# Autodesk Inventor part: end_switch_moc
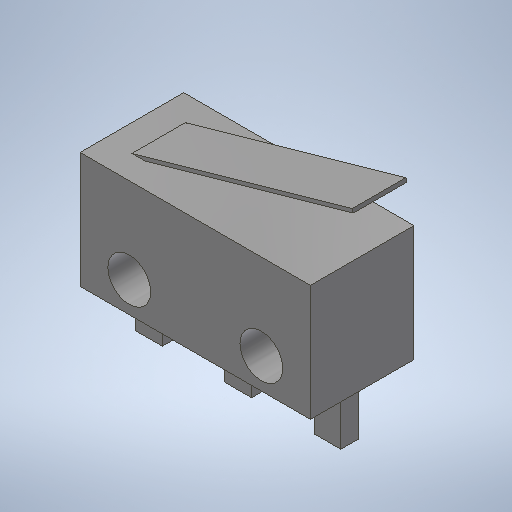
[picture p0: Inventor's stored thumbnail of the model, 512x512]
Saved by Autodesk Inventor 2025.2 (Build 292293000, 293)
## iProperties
Created: 2025-04
Part Number: end_switch_moc
Material: 1.0037 S235JR
Document SubType Name: Modeling
Designer: BennF
Density: 7.85 g/cm^3
Appearance: Stahl
Author: BennF
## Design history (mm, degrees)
sketch "Sketch2"
  geometry: L1 (6.45, 3.25)-(-6.45, 3.25); L2 (-6.45, 3.25)-(-6.45, -3.25); L3 (-6.45, -3.25)-(6.45, -3.25); L4 (6.45, -3.25)-(6.45, 3.25); 3 further points
  constraints: 8 end point, 2 midpoint, 2 parallel, 1 horizontal, 1 horizontal alignment, 1 perpendicular, 1 vertical alignment
  dimensions: "d0" = 12.9 distance of L1.start L1.end; "d1" = 6.5 distance of L3.end L1.start
extrude "Extrusion1" new body sketch "Sketch2" stored distance "d2" = 5.8; taper "d3" = 0 deg
sketch "Sketch3"
  geometry: L1 (-3.7, -1.55)-(3.7, -1.55); L2 (-6.45, -3.25)-(6.45, -3.25) reference; 2 further points
  constraints: 2 end point, 1 horizontal, 1 horizontal alignment, 1 midpoint, 1 vertical alignment
  dimensions: "d11" = 7.4 distance of L1.start L1.end; "d12" = 1.7 distance between parallel lines of L2 L1 (computed from d4)
hole "Hole1" sketch "Sketch3" at (-3.7, -1.55), (3.7, -1.55) diameter "d4" = 2.4; stored, may be unused: countersink angle "d8" = 90 deg, drill point angle "d10" = 0 deg; dims "d5" = 6, "d6" = 4, "d7" = 2, "d9" = 8
sketch "Sketch4"
  geometry: L1 (12.2, -3.4)-(10.7, -3.4); L2 (10.7, -3.4)-(10.7, -2.4); L3 (10.7, -2.4)-(12.2, -2.4); L4 (12.2, -2.4)-(12.2, -3.4); L5 (7.2, -3.4)-(5.7, -3.4); L6 (5.7, -3.4)-(5.7, -2.4); L7 (5.7, -2.4)-(7.2, -2.4); L8 (7.2, -2.4)-(7.2, -3.4); L9 (2.2, -3.4)-(0.7, -3.4); L10 (0.7, -3.4)-(0.7, -2.4); L11 (0.7, -2.4)-(2.2, -2.4); L12 (2.2, -2.4)-(2.2, -3.4); L13 (10.7, -2.9)-(7.2, -2.9); L14 (8.95, 0)-(8.95, -5.8) reference; L15 (5.7, -2.9)-(2.2, -2.9); 4 further points
  constraints: 28 end point, 7 midpoint, 6 parallel, 5 perpendicular, 4 equal length, 3 horizontal, 3 horizontal alignment, 3 point on line, 1 vertical alignment
  dimensions: "d13" = 1 distance of L3.end L1.start; "d14" = 1.5 distance of L1.start L1.end; "d15" = 10 distance of point (1.45, -3.4) point (11.45, -3.4)
extrude "Extrusion2" join sketch "Sketch4" distance "d16" = 3; taper "d17" = 0 deg
sketch "Sketch5"
  geometry: L1 (6.45, 3.25)-(-6.45, 3.25) reference; L2 (4.95, 3.25)-(-7.395, 6.75); L3 (-7.395, 6.75)-(-7.45, 6.558); L4 (-7.45, 6.558)-(4.217, 3.25); L5 (6.45, -3.25)-(6.45, 3.25) reference; L6 (-6.45, 3.25)-(-6.45, -3.25) reference; L7 (-6.45, -3.25)-(6.45, -3.25) reference; 1 further point
  constraints: 6 end point, 2 point on line, 1 parallel, 1 perpendicular
  dimensions: "d18" = 0.2 distance between parallel lines of L4 L2; "d19" = 1.5 distance from line of L2.start L5; "d20" = 1 distance from line of L6 L3.end; "d21" = 10 distance from line of L7 L2.end
extrude "Extrusion3" join sketch "Sketch5" stored distance "d22" = 3; taper "d23" = 0 deg
body "Solid1"
